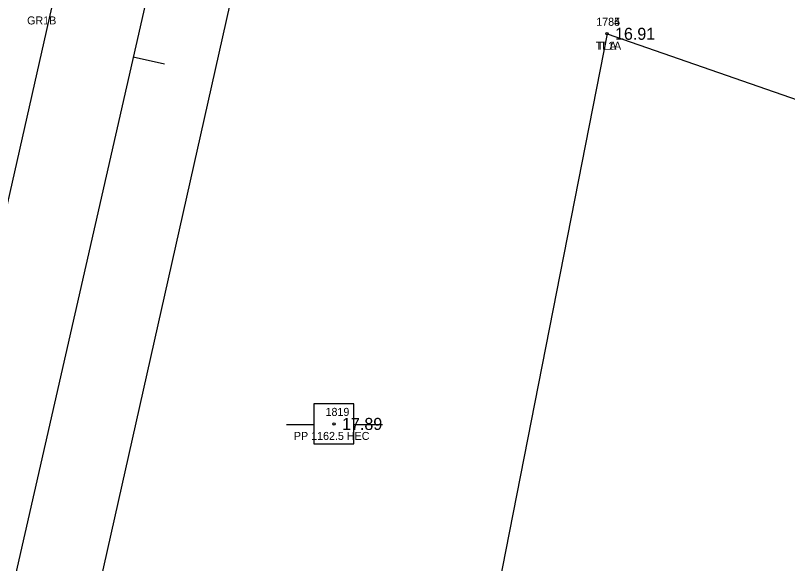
# Model space of a CAD drawing. Extents: x 2654414 to 2656963, y 761776 to 764965.
# Drawn here: x 2655685.5 to 2655781.9, y 763113.6 to 763182 of the extents above; entities that cross this region are included whole.
import ezdxf

# ---------------------------------------------------------------- set-up
doc = ezdxf.new("R2010")
doc.units = 0
for name, color, linetype in [('Default', 7, 'Continuous'), ('RD_EX_GuardRail_txCode', 7, 'Continuous'), ('RD_EX_Road', 7, 'Continuous'), ('RD_EX_TX_VEG_ELEV', 7, 'Continuous'), ('RD_EX_UT', 7, 'Continuous'), ('RD_EX_UT_txCode', 7, 'Continuous'), ('RD_EX_VEG', 7, 'Continuous'), ('RD_EX_VEG_txCode', 7, 'Continuous'), ('RD_HC_Cl', 7, 'Continuous'), ('RD_HC_Data_Tic', 7, 'Continuous'), ('RD_HC_Survey_ELEV', 7, 'Continuous'), ('RD_SMD_Locator', 7, 'Continuous')]:
    doc.layers.add(name, color=color, linetype=linetype)

msp = doc.modelspace()

# ---------------------------------------------------------------- linework, layer by layer
at = {"layer": 'Default'}
msp.add_line((2656050.51, 764712.367), (2655383.263, 761787.511), dxfattribs=at)
at = {"layer": 'RD_EX_Road'}
for points in [[(2655700.994, 763232.279), (2655693.552, 763198.573), (2655671.649, 763102.037), (2655649.038, 763001.061), (2655627.271, 762906.233), (2655604.996, 762809.365), (2655598.992, 762783.09), (2655583.655, 762714.137), (2655561.97, 762618.323), (2655556.356, 762593.843), (2655548.114, 762557.141), (2655540.102, 762522.478), (2655518.03, 762425.04), (2655496.479, 762329.558), (2655475.552, 762236.625), (2655473.199, 762226.142), (2655466.574, 762197.504), (2655460.058, 762168.164), (2655454.261, 762143.776), (2655432.5, 762049.878), (2655410.7, 761955.515), (2655388.166, 761858.426), (2655373.501, 761793.951)], [(2655722.661, 763227.867), (2655714.474, 763193.228), (2655692.888, 763097.257), (2655670.037, 762995.178), (2655648.569, 762900.673)]]:
    msp.add_lwpolyline(points, dxfattribs=at)
at = {"layer": 'RD_EX_UT'}
for p, q in [((2655727.775, 763133.529), (2655722.775, 763133.529)), ((2655722.775, 763133.529), (2655722.775, 763128.529)), ((2655727.775, 763128.529), (2655727.775, 763133.529)), ((2655719.344, 763130.966), (2655722.813, 763130.966)), ((2655727.703, 763130.966), (2655731.344, 763130.966)), ((2655722.775, 763128.529), (2655727.775, 763128.529))]:
    msp.add_line(p, q, dxfattribs=at)
at = {"layer": 'RD_EX_VEG'}
msp.add_line((2655759.379, 763179.693), (2655808.503, 763162.639), dxfattribs=at)
msp.add_lwpolyline([(2655759.379, 763179.693), (2655740.402, 763083.125), (2655695.658, 762892.972), (2655758.369, 762873.588)], dxfattribs=at)
at = {"layer": 'RD_HC_Cl'}
msp.add_line((2656050.51, 764712.367), (2655383.263, 761787.511), dxfattribs=at)
at = {"layer": 'RD_HC_Data_Tic'}
msp.add_line((2655700.206, 763176.818), (2655704.105, 763175.928), dxfattribs=at)
at = {"layer": 'RD_SMD_Locator'}
for centre in [(2655759.379, 763179.693), (2655759.379, 763179.693), (2655725.284, 763131.02)]:
    msp.add_circle(centre, 0.15, dxfattribs=at)

# ---------------------------------------------------------------- texts
at = {"layer": 'RD_EX_GuardRail_txCode'}
msp.add_text('GR1B', height=1, dxfattribs=at).set_placement((2655686.947, 763180.859))
at = {"layer": 'RD_EX_TX_VEG_ELEV'}
msp.add_text('16.91', height=1.5, dxfattribs=at).set_placement((2655760.379, 763178.943))
msp.add_text('16.91', height=1.5, dxfattribs=at).set_placement((2655760.379, 763178.943))
at = {"layer": 'RD_EX_UT_txCode'}
for s, p in [('1819', (2655724.221, 763132.02)), ('PP 1162.5 HEC', (2655720.268, 763129.02))]:
    msp.add_text(s, height=1, dxfattribs=at).set_placement(p)
at = {"layer": 'RD_EX_VEG_txCode'}
for s, p in [('1784', (2655758.033, 763180.693)), ('1785', (2655758.033, 763180.693)), ('TL1A', (2655757.954, 763177.693)), ('TLA', (2655758.119, 763177.693))]:
    msp.add_text(s, height=1, dxfattribs=at).set_placement(p)
at = {"layer": 'RD_HC_Survey_ELEV'}
msp.add_text('17.89', height=1.5, dxfattribs=at).set_placement((2655726.284, 763130.27))

doc.saveas('drawing.dxf')
